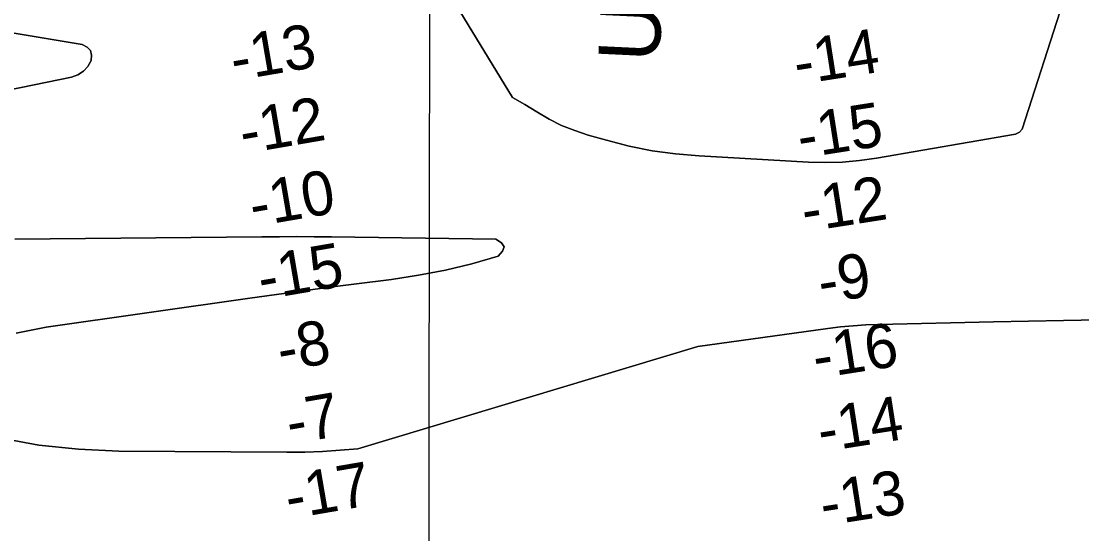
# Model space of a CAD drawing. Extents: x 3219052 to 3256913, y 800770 to 826146.
# Drawn here: x 3227918 to 3229358, y 816190 to 816886 of the extents above; entities that cross this region are included whole.
import ezdxf

# ---------------------------------------------------------------- set-up
doc = ezdxf.new("R2010")
doc.units = 0
for name, color, linetype in [('V-GRID-MAJR', 7, 'Continuous'), ('V-RIVR-RANG', 7, 'Continuous'), ('V-RIVR-RANG-IDEN', 7, 'Continuous'), ('V-TOPO-DPTH', 7, 'Continuous'), ('V-TOPO-MINR', 7, 'Continuous')]:
    doc.layers.add(name, color=color, linetype=linetype)

msp = doc.modelspace()

# ---------------------------------------------------------------- linework, layer by layer
at = {"layer": 'V-GRID-MAJR'}
msp.add_spline([(3228457.1, 806177.4), (3228466, 812237.7), (3228474.8, 818299.9), (3228483.6, 824362.1), (3228483.6, 824364)], degree=3, dxfattribs=at)
at = {"layer": 'V-TOPO-DPTH'}
for points in [[(3229332.2, 816912.4), (3229276.6, 816739.1), (3229272.9, 816735.4), (3229267.5, 816732.6), (3229078.7, 816699.7), (3229055.7, 816696.6), (3229032.7, 816694.4), (3229009.6, 816693.9), (3228986.4, 816694.4), (3228838.2, 816702.9), (3228806.2, 816705.8), (3228774.5, 816710), (3228743.2, 816716.4), (3228712.1, 816724.2), (3228687.3, 816731.2), (3228669.1, 816737.3), (3228651.4, 816744.4), (3228634.4, 816753.1), (3228617.9, 816762.8), (3228601.4, 816772.8), (3228584.6, 816782.1), (3228475.6, 816961.5)], [(3229332.2, 816912.4), (3229276.6, 816739.1), (3229272.9, 816735.4), (3229267.5, 816732.6), (3229078.7, 816699.7), (3229055.7, 816696.6), (3229032.7, 816694.4), (3229009.6, 816693.9), (3228986.4, 816694.4), (3228838.2, 816702.9), (3228806.2, 816705.8), (3228774.5, 816710), (3228743.2, 816716.4), (3228712.1, 816724.2), (3228687.3, 816731.2), (3228669.1, 816737.3), (3228651.4, 816744.4), (3228634.4, 816753.1), (3228617.9, 816762.8), (3228601.4, 816772.8), (3228584.6, 816782.1), (3228475.6, 816961.5)], [(3227902.5, 816870.6), (3228000.4, 816854.2), (3228007.1, 816850.8), (3228011.7, 816846.2), (3228013.2, 816839.9), (3228012.7, 816832.5), (3228008, 816824.5), (3228002.1, 816817.9), (3227994.6, 816813.3), (3227985.9, 816810.1), (3227813.3, 816774.8)], [(3227813.3, 816774.8), (3227985.9, 816810.1), (3227994.6, 816813.3), (3228002.1, 816817.9), (3228008, 816824.5), (3228012.7, 816832.5), (3228013.2, 816839.9), (3228011.7, 816846.2), (3228007.1, 816850.8), (3228000.4, 816854.2), (3227902.5, 816870.6)], [(3227909.1, 816589.8), (3228244.5, 816593.1), (3228268.1, 816593.2), (3228291.7, 816593.3), (3228315.3, 816593.2), (3228338.8, 816592.9), (3228561.9, 816589.8), (3228569.7, 816585.1), (3228573.5, 816579.7), (3228571.3, 816573.5), (3228565.3, 816566.7), (3228529.5, 816556.6), (3228493.5, 816547.8), (3228457.1, 816540.9), (3228420.4, 816535.2), (3228373, 816529.2), (3228336.8, 816524.5), (3228300.6, 816519.7), (3228264.4, 816514.7), (3228228.2, 816509.7), (3227951.3, 816470.2), (3227910.6, 816462.1)], [(3227909.1, 816589.8), (3228244.5, 816593.1), (3228268.1, 816593.2), (3228291.7, 816593.3), (3228315.3, 816593.2), (3228338.8, 816592.9), (3228561.9, 816589.8), (3228569.7, 816585.1), (3228573.5, 816579.7), (3228571.3, 816573.5), (3228565.3, 816566.7), (3228529.5, 816556.6), (3228493.5, 816547.8), (3228457.1, 816540.9), (3228420.4, 816535.2), (3228373, 816529.2), (3228336.8, 816524.5), (3228300.6, 816519.7), (3228264.4, 816514.7), (3228228.2, 816509.7), (3227951.3, 816470.2), (3227910.6, 816462.1)], [(3227887.8, 816320), (3227941.4, 816310.1), (3227995.6, 816304.6), (3228050.3, 816302), (3228278.4, 816300.5), (3228302.5, 816300.8), (3228326.6, 816301.5), (3228350.7, 816303.1), (3228374.7, 816305.2), (3228836.4, 816444.3), (3229012.7, 816468.7), (3229029.9, 816470.7), (3229047.1, 816472.4), (3229064.4, 816473.5), (3229081.7, 816474.1), (3229237.7, 816477.4), (3229333, 816479.4), (3229428.4, 816481.4)], [(3227887.8, 816320), (3227941.4, 816310.1), (3227995.6, 816304.6), (3228050.3, 816302), (3228278.4, 816300.5), (3228302.5, 816300.8), (3228326.6, 816301.5), (3228350.7, 816303.1), (3228374.7, 816305.2), (3228836.4, 816444.3), (3229012.7, 816468.7), (3229029.9, 816470.7), (3229047.1, 816472.4), (3229064.4, 816473.5), (3229081.7, 816474.1), (3229237.7, 816477.4), (3229333, 816479.4), (3229428.4, 816481.4)]]:
    msp.add_lwpolyline(points, dxfattribs=at)
at = {"layer": 'V-TOPO-MINR'}
for points in [[(3228475.6, 816961.5), (3228584.6, 816782.1), (3228601.4, 816772.8), (3228617.9, 816762.8), (3228634.4, 816753.1), (3228651.4, 816744.4), (3228669.1, 816737.3), (3228687.3, 816731.2), (3228712.1, 816724.2), (3228743.2, 816716.4), (3228774.5, 816710), (3228806.2, 816705.8), (3228838.2, 816702.9), (3228986.4, 816694.4), (3229009.6, 816693.9), (3229032.7, 816694.4), (3229055.7, 816696.6), (3229078.7, 816699.7), (3229267.5, 816732.6), (3229272.9, 816735.4), (3229276.6, 816739.1), (3229332.2, 816912.4)], [(3227813.3, 816774.8), (3227985.9, 816810.1), (3227994.6, 816813.3), (3228002.1, 816817.9), (3228008, 816824.5), (3228012.7, 816832.5), (3228013.2, 816839.9), (3228011.7, 816846.2), (3228007.1, 816850.8), (3228000.4, 816854.2), (3227902.5, 816870.6)], [(3227910.6, 816462.1), (3227951.3, 816470.2), (3228228.2, 816509.7), (3228264.4, 816514.7), (3228300.6, 816519.7), (3228336.8, 816524.5), (3228373, 816529.2), (3228420.4, 816535.2), (3228457.1, 816540.9), (3228493.5, 816547.8), (3228529.5, 816556.6), (3228565.3, 816566.7), (3228571.3, 816573.5), (3228573.5, 816579.7), (3228569.7, 816585.1), (3228561.9, 816589.8), (3228338.8, 816592.9), (3228315.3, 816593.2), (3228291.7, 816593.3), (3228268.1, 816593.2), (3228244.5, 816593.1), (3227909.1, 816589.8)], [(3229428.4, 816481.4), (3229333, 816479.4), (3229237.7, 816477.4), (3229081.7, 816474.1), (3229064.4, 816473.5), (3229047.1, 816472.4), (3229029.9, 816470.7), (3229012.7, 816468.7), (3228836.4, 816444.3), (3228374.7, 816305.2), (3228350.7, 816303.1), (3228326.6, 816301.5), (3228302.5, 816300.8), (3228278.4, 816300.5), (3228050.3, 816302), (3227995.6, 816304.6), (3227941.4, 816310.1), (3227887.8, 816320)]]:
    msp.add_lwpolyline(points, dxfattribs=at)

# ---------------------------------------------------------------- texts
at = {"layer": 'V-RIVR-RANG'}
for s, rotation, p in [('-13', 9.7619, (3228206.8, 816804.7)), ('-14', 8.909, (3228971.1, 816799.4)), ('-12', 9.7619, (3228219.2, 816705.5)), ('-15', 8.909, (3228975.9, 816699.4)), ('-10', 9.7619, (3228232.7, 816606.5)), ('-12', 8.909, (3228981.5, 816599.5)), ('-15', 9.7619, (3228244, 816507.1)), ('-9', 8.909, (3229004, 816502.2)), ('-8', 9.7619, (3228270.3, 816410.3)), ('-16', 8.909, (3228996.8, 816400.3)), ('-7', 9.7619, (3228282.7, 816311.1)), ('-14', 8.909, (3229003.5, 816300.5)), ('-17', 9.7619, (3228281.2, 816209.5)), ('-13', 8.909, (3229006.9, 816200.2))]:
    msp.add_text(s, height=60, rotation=rotation, dxfattribs=at).set_placement(p)
at = {"layer": 'V-RIVR-RANG-IDEN'}
msp.add_text('U-30', height=83, rotation=87.273, dxfattribs=at).set_placement((3228783.9, 816829.3))

doc.saveas('drawing.dxf')
